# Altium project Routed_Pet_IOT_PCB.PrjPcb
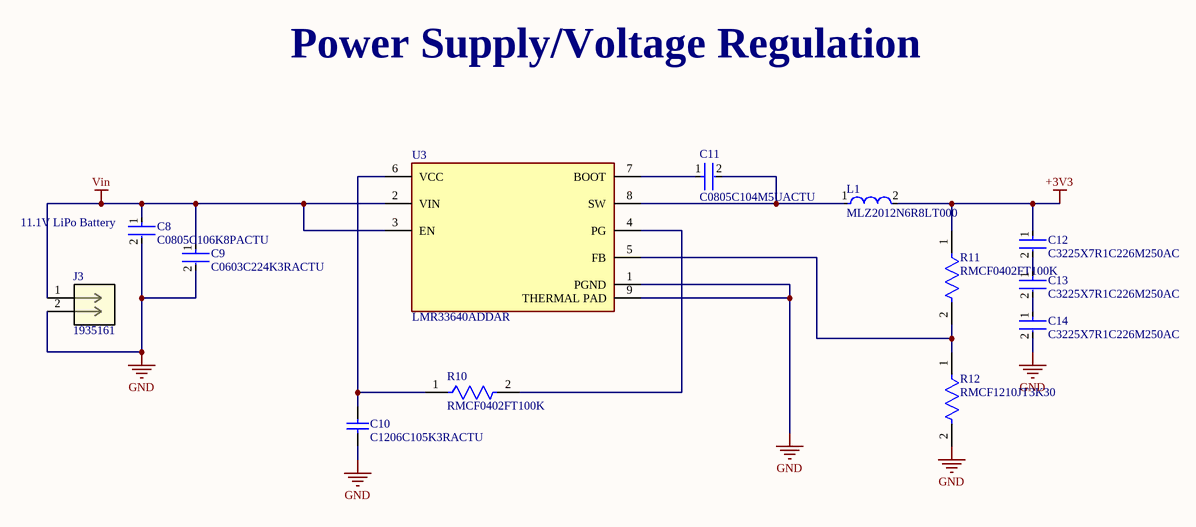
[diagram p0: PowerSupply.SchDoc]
3 sheets, 38 parts. Net scope: global (net labels, ports and power ports of the same name join across sheets).
Board file: PetTrackerPCB.PcbDoc
Sheets:
  PowerSupply.SchDoc
  Dataflow.SchDoc
  EC25.SchDoc

## Sheet PowerSupply.SchDoc
size A; SheetNumber: 1; SheetTotal: 3

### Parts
C8  C0805C106K8PACTU  [FP-C0805C-DG-MFG]
C9  C0603C224K3RACTU  [FP-C0603C-CF-MFG]
C10  C1206C105K3RACTU  [CAPC3216X180X50ML20T25]
C11  C0805C104M5UACTU  [FP-C0805C104M5UACTU-MFG]
C12  C3225X7R1C226M250AC  [FP-C3225-250-0_4-IPC_B]
C13  C3225X7R1C226M250AC  [FP-C3225-250-0_4-IPC_B]
C14  C3225X7R1C226M250AC  [FP-C3225-250-0_4-IPC_B]
J3  1935161  [CONN_1935161_PXC]
L1  MLZ2012N6R8LT000  [FP-MLZ2012-0_85-IPC_A]
R10  RMCF0402FT100K  [FP-RMCF0402-IPC_C]
R11  RMCF0402FT100K  [FP-RMCF0402-IPC_C]
R12  RMCF1210JT3K30  [FP-RMCF1210-IPC_A]
U3  LMR33640ADDAR  [FP-DDA0008J-IPC_A]

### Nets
+3V3: C12.1 L1.2 R11.1
GND: C8.2 C9.2 C10.1 C14.2 J3.2 R12.2 U3.1(PGND) U3.9(THERMAL_PAD)
Vin: C8.1 C9.1 J3.1 U3.2(VIN) U3.3(EN)
NetC10_2: C10.2 R10.1 U3.6(VCC)
NetC11_1: C11.1 U3.7(BOOT)
NetC11_2: C11.2 L1.1 U3.8(SW)
NetC12_2: C12.2 C13.1
NetC13_2: C13.2 C14.1
NetR10_2: R10.2 U3.4(PG)
NetR11_2: R11.2 R12.1 U3.5(FB)

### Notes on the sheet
- Power Supply/Voltage Regulation
- (near C8) 11.1V LiPo Battery

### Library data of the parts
C8 = CMP-2007-03243-2: CAP CER 10UF 10V X5R 0805; Manufacturer: Kemet; 3DS Part Number: 220-00001; Tolerance: 10%; Temperature Coefficient: 15%; Material: Ceramic
C9 = CMP-2006-03146-2: CAP CER 0.22UF 25V 10% X7R 0603; Manufacturer: KEMET; Temperature Coefficient: 30ppm/°C; Value: 0.22 μF; Material: Ceramic; Description: C0603 0.22 μF X7R 30ppm/°C 10.00% 25 V; Tolerance: 0.1; Automotive Grade: Grade 1
C10 = CMP-2000-04991-1: Chip Capacitor, 1 uF, +/- 10%, 25 V, -55 to 125 degC, 1206 (3216 Metric), RoHS, Tape and Reel; Manufacturer: Kemet; Temperature Coefficient / Code: +/-15%; Capacitance: 1uF; Dielectric: X7R; Voltage Rating DC: 25V; Capacitance - nF: 1000nF; Class: Class1; Case Length: 3.2mm; Type: SMDMLCCX7R6.3-250VDCCommericalGrade; Case Width: 1.6mm
C11 = CMP-2007-03742-2: CAP CER 0.1UF 50V Z5U 0805; Dielectric Material: Ceramic; Tolerance: 20%; Dissipation Factor: 4%; Capacitance: 100nF
C12-C14 = CMP-2000-06052-2: Multilayer Ceramic Capacitors 22uF ±20% 16V X7R SMD 1210
J3 = 1935161: Ceramic Capacitor, Multilayer, Ceramic, 16V, 10% +Tol, 10% -Tol, X5R, 15% TC, 10uF, Surface Mount, 0805; Mfr_Name: Phoenix Contact; Manufacturer: Samsung; Manufacturer Part Number: CL21A106KOQNNNE; Multilayer: Yes
L1 = CMP-08253-000092-1: Shielded Multilayer Inductor 6.8uH ±20% 550mA 325mΩ SMD 0805; Test Frequency: 2MHz; Self Resonant Frequency: 60MHz; Saturation Current: 110mA; Core Material: Ferrite; DC Resistance (DCR): 250mR
R10 R11 = CMP-2000-06984-2: 100kΩ ±1% 0.063W 0402 Thick Film Chip Resistor AEC-Q200 compliant; Max Power Dissipation: 63mW; Resistance: 100kR; Temperature Coefficient: 100ppm/°C; Power Rating: 62.5mW
R12 = CMP-26527-001928-1: 3.3kΩ ±5% 0.5W 1210 Thick Film Chip Resistor AEC-Q200 compliant; Temperature Coefficient: 200ppm/°C; Resistance: 3.3kR; Max Power Dissipation: 333mW
U3 = CMP-04918-000399-1: 36V 4A 400KHZ REGULATOR

## Sheet Dataflow.SchDoc
size A3; SheetNumber: 2; SheetTotal: 3
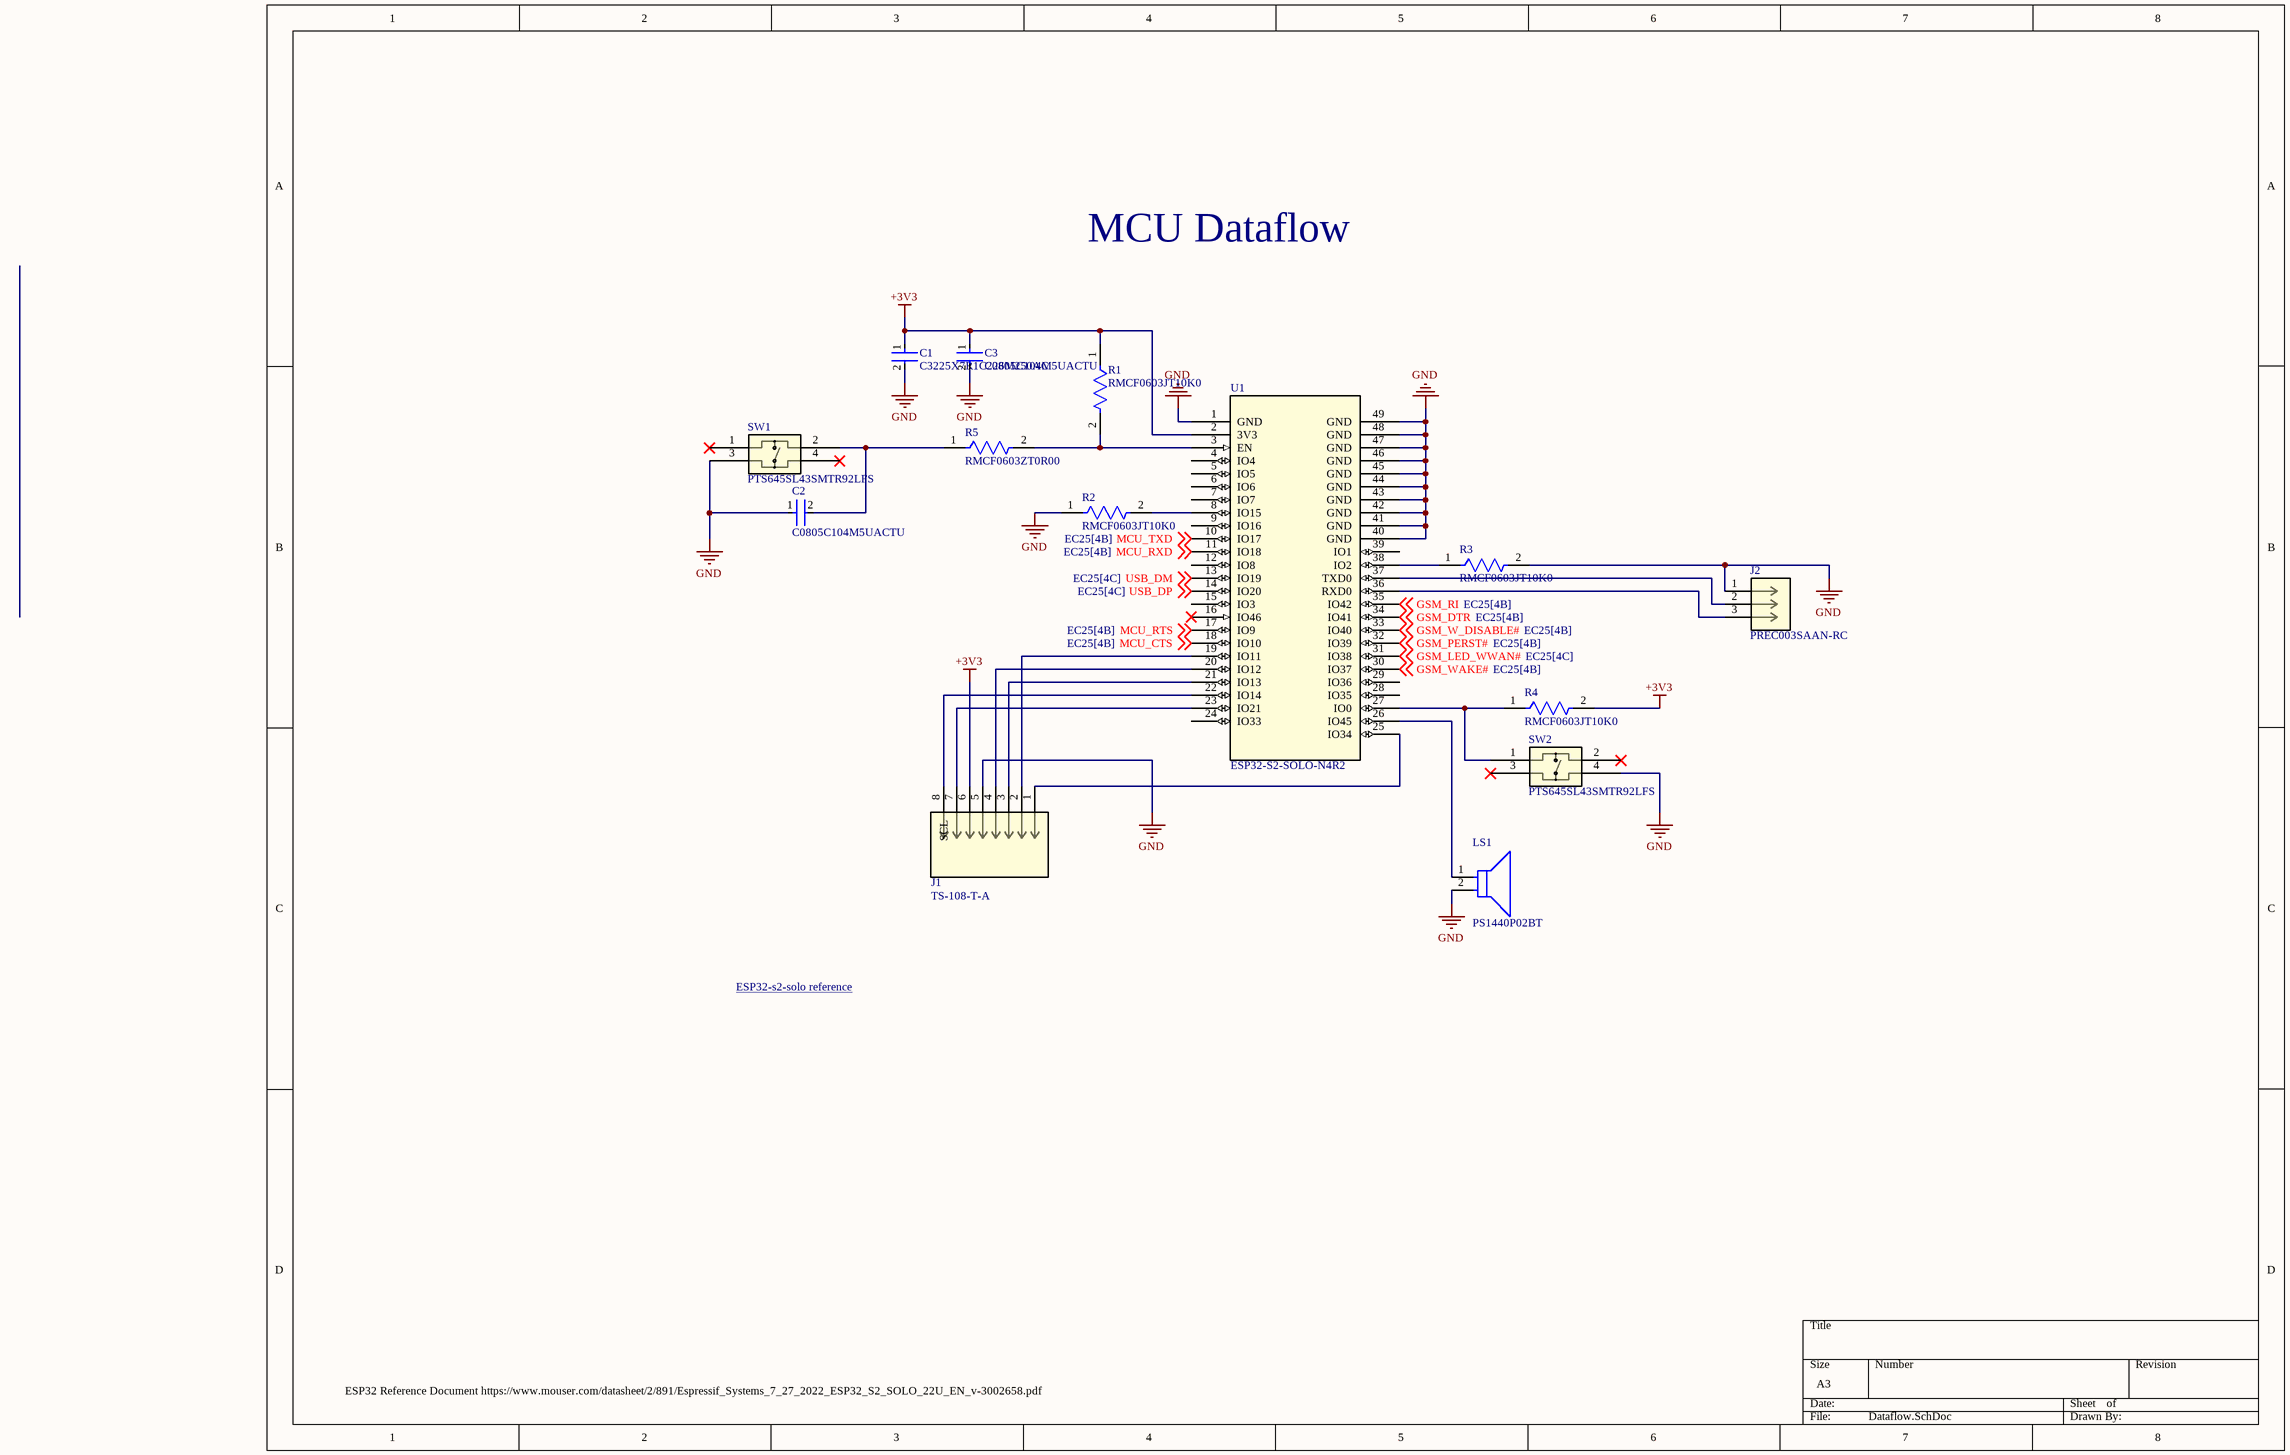
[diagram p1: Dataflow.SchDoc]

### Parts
C1  C3225X7R1C226M250AC  [FP-C3225-250-0_4-IPC_B]
C2  C0805C104M5UACTU  [FP-C0805C104M5UACTU-MFG]
C3  C0805C104M5UACTU  [FP-C0805C104M5UACTU-MFG]
J1  TS-108-T-A  [CON8_1X8_TU_HTS_SAI]
J2  PREC003SAAN-RC  [CONN_PREC003SAAN-RC_SUL]
LS1  PS1440P02BT  [FP-PS1440P02BT-MFG]
R1  RMCF0603JT10K0  [FP-RMCF0603-IPC_C]
R2  RMCF0603JT10K0  [FP-RMCF0603-IPC_C]
R3  RMCF0603JT10K0  [FP-RMCF0603-IPC_C]
R4  RMCF0603JT10K0  [FP-RMCF0603-IPC_C]
R5  RMCF0603ZT0R00  [FP-RMCF0603-MFG]
SW1  PTS645SL43SMTR92LFS  [PTS645SL43SMTR92LFS_CNK]
SW2  PTS645SL43SMTR92LFS  [PTS645SL43SMTR92LFS_CNK]
U1  ESP32-S2-SOLO-N4R2  [MOD41_ESP32-S2-SOLO_EXP]

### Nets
+3V3: C1.1 C3.1 J1.6(+3V3) R1.1 R4.2 U1.2(3V3)
GND: C1.2 C2.1 C3.2 J1.5(GND) J2.1 LS1.2 R2.1 R3.2 SW1.3 SW2.4 U1.1(GND) U1.40(GND) U1.41(GND) U1.42(GND) U1.43(GND) U1.44(GND) U1.45(GND) U1.46(GND) U1.47(GND) U1.48(GND) U1.49(GND)
GSM_DTR: U1.34(IO41) ; off-sheet GSM_DTR
GSM_LED_WWAN#: U1.31(IO38) ; off-sheet GSM_LED_WWAN#
GSM_PERST#: U1.32(IO39) ; off-sheet GSM_PERST#
GSM_RI: U1.35(IO42) ; off-sheet GSM_RI
GSM_W_DISABLE#: U1.33(IO40) ; off-sheet GSM_W_DISABLE#
GSM_WAKE#: U1.30(IO37) ; off-sheet GSM_WAKE#
MCU_CTS: U1.18(IO10) ; off-sheet MCU_CTS
MCU_RTS: U1.17(IO9) ; off-sheet MCU_RTS
MCU_RXD: U1.11(IO18) ; off-sheet MCU_RXD
MCU_TXD: U1.10(IO17) ; off-sheet MCU_TXD
USB_DM: U1.13(IO19) ; off-sheet USB_DM
USB_DP: U1.14(IO20) ; off-sheet USB_DP
NetC2_2: C2.2 R5.1 SW1.2
NetJ1_1: J1.1(CS) U1.25(IO34)
NetJ1_2: J1.2(MOSI) U1.19(IO11)
NetJ1_3: J1.3(MISO) U1.21(IO13)
NetJ1_4: J1.4(SCLK) U1.20(IO12)
NetJ1_7: J1.7(SDA) U1.23(IO21)
NetJ1_8: J1.8(SCL) U1.22(IO14)
NetJ2_2: J2.2 U1.37(TXD0)
NetJ2_3: J2.3 U1.36(RXD0)
NetLS1_1: LS1.1 U1.26(IO45)
NetR1_2: R1.2 R5.2 U1.3(EN)
NetR2_2: R2.2 U1.8(IO15)
NetR3_1: R3.1 U1.38(IO2)
NetR4_1: R4.1 SW2.1 U1.27(IO0)

Not connected (* = marked no-connect by the designer): SW1 1* 4*; SW2 2* 3*; U1 4(IO4) 5(IO5) 6(IO6) 7(IO7) 9(IO16) 12(IO8) 15(IO3) 16(IO46)* 24(IO33) 28(IO35) 29(IO36) 39(IO1)

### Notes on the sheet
- MCU Dataflow
- ESP32-s2-solo reference <https://www.espressif.com/sites/default/files/documentation/esp32-s2-solo-2_esp32-s2-solo-2u_datasheet_en.pdf>
- ESP32 Reference Document https://www.mouser.com/datasheet/2/891/Espressif_Systems_7_27_2022_ESP32_S2_SOLO_22U_EN_v-3002658.pdf

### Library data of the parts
C1 = CMP-2000-06052-2: as C12 on sheet PowerSupply
C2 C3 = CMP-2007-03742-2: as C11 on sheet PowerSupply
J1 = TS-108-T-A: No Description Available; Mfr_Name: Samtec Inc
J2 = PREC003SAAN-RC: No Description Available; Mfr_Name: Sullins
LS1 = CMP-08413-000003-1: AUDIO PIEZO TRANSDUCER 30V TH; Self Resonant Frequency: 4kHz; Washable: No; Voltage Rating (DC): 3V; Number of Terminals/Pins: 2
R1-R4 = CMP-26527-002098-1: 10kΩ ±5% 0.1W 0603 Thick Film Chip Resistor AEC-Q200 compliant; Power Rating: 100mW; Temperature Coefficient: 100ppm/°C; Resistance: 10kR
R5 = CMP-26527-000011-1: RES 0 OHM JUMPER 1/10W 0603; Manufacturer: Stackpole; Power Rating: 0.1W; Voltage Rating: 75V; Resistance: 0mΩ; Automotive Grade: Grade 0; Value: 0mΩ
SW1 SW2 = PTS645SL43SMTR92LFS: No Description Available; Mfr_Name: C&K Components
U1 = ESP32-S2-SOLO-N4R2: No Description Available; Mfr_Name: Espressif Systems

## Sheet EC25.SchDoc
size A3; SheetNumber: 3; SheetTotal: 3
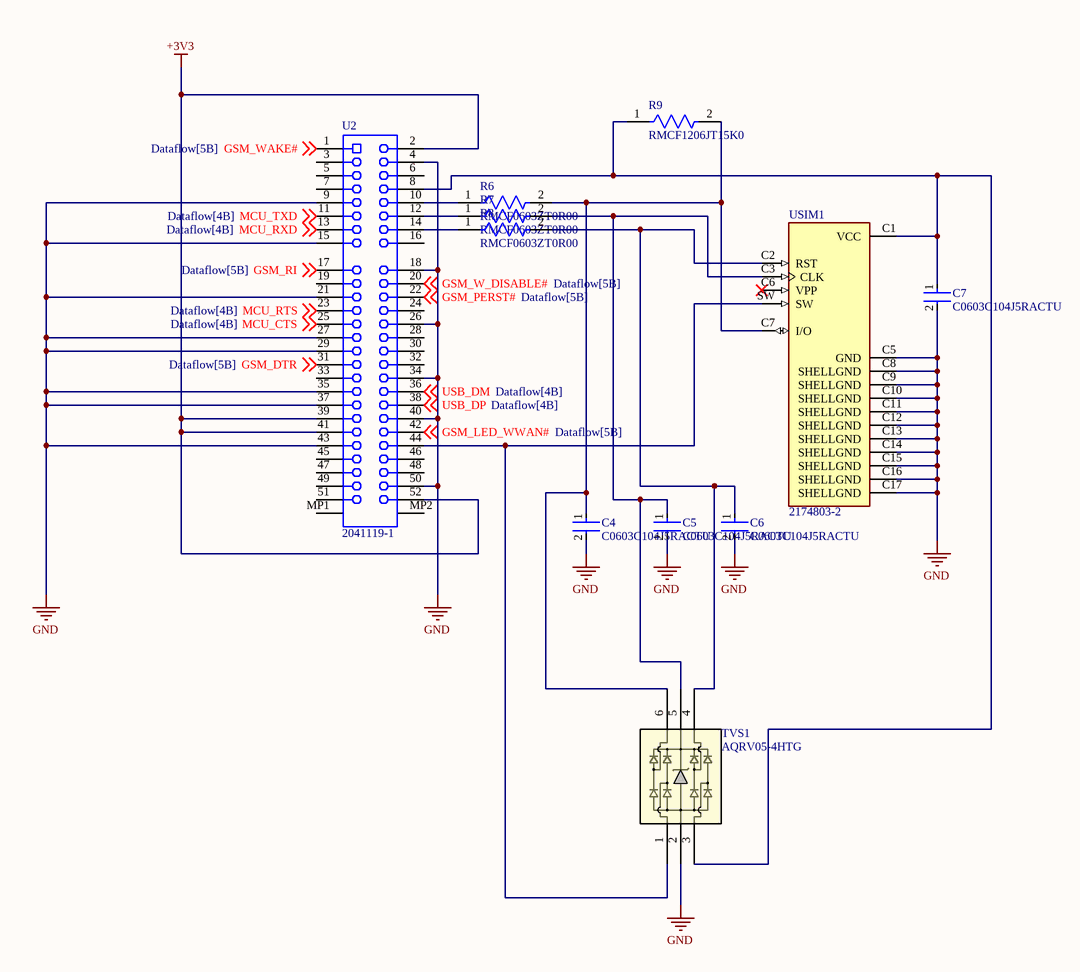
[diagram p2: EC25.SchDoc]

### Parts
C4  C0603C104J5RACTU  [FP-C0603C-CF-MFG]
C5  C0603C104J5RACTU  [FP-C0603C-CF-MFG]
C6  C0603C104J5RACTU  [FP-C0603C-CF-MFG]
C7  C0603C104J5RACTU  [FP-C0603C-CF-MFG]
R6  RMCF0603ZT0R00  [FP-RMCF0603-MFG]
R7  RMCF0603ZT0R00  [FP-RMCF0603-MFG]
R8  RMCF0603ZT0R00  [FP-RMCF0603-MFG]
R9  RMCF1206JT15K0  [FP-RMCF1206-IPC_A]
TVS1  AQRV05-4HTG  [SOT23-6_LTF]
U2  2041119-1  [TECO-2041119-1_3_V]
USIM1  2174803-2  [CONN_2174803-2]

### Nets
+3V3: U2.2 U2.39 U2.41 U2.52
GND: C4.2 C5.2 C6.2 C7.2 TVS1.2 U2.4 U2.9 U2.15 U2.18 U2.21 U2.26 U2.27 U2.29 U2.34 U2.35 U2.37 U2.40 U2.43 U2.50 USIM1.C5(GND) USIM1.C8(SHELLGND) USIM1.C9(SHELLGND) USIM1.C10(SHELLGND) USIM1.C11(SHELLGND) USIM1.C12(SHELLGND) USIM1.C13(SHELLGND) USIM1.C14(SHELLGND) USIM1.C15(SHELLGND) USIM1.C16(SHELLGND) USIM1.C17(SHELLGND)
GSM_DTR: U2.31 ; off-sheet GSM_DTR
GSM_LED_WWAN#: U2.42 ; off-sheet GSM_LED_WWAN#
GSM_PERST#: U2.22 ; off-sheet GSM_PERST#
GSM_RI: U2.17 ; off-sheet GSM_RI
GSM_W_DISABLE#: U2.20 ; off-sheet GSM_W_DISABLE#
GSM_WAKE#: U2.1 ; off-sheet GSM_WAKE#
MCU_CTS: U2.25 ; off-sheet MCU_CTS
MCU_RTS: U2.23 ; off-sheet MCU_RTS
MCU_RXD: U2.13 ; off-sheet MCU_RXD
MCU_TXD: U2.11 ; off-sheet MCU_TXD
USB_DM: U2.36 ; off-sheet USB_DM
USB_DP: U2.38 ; off-sheet USB_DP
NetC4_1: C4.1 R6.2 R9.2 TVS1.6 USIM1.C7(I/O)
NetC5_1: C5.1 R7.2 TVS1.5 USIM1.C3(CLK)
NetC6_1: C6.1 R8.2 TVS1.4 USIM1.C2(RST)
NetC7_1: C7.1 R9.1 TVS1.3 U2.8 USIM1.C1(VCC)
NetR6_1: R6.1 U2.10
NetR7_1: R7.1 U2.12
NetR8_1: R8.1 U2.14
NetTVS1_1: TVS1.1 U2.44 USIM1.SW

Not connected (* = marked no-connect by the designer): U2 3 5 6 7 16 19 24 28 30 32 33 45 46 47 48 49 51 MP1 MP2; USIM1 C6(VPP)*

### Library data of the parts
C4-C7 = CMP-2006-03056-2: CAP CER 0.1UF 50V 5% X7R 0603; Manufacturer: KEMET; Automotive Grade: Grade 1; Tolerance: 0.05; Capacitance: 0.10 μF; Value: 0.10 μF; Material: Ceramic; Temperature Coefficient: 30ppm/°C; Description: C0603 0.10 μF X7R 30ppm/°C 5.00% 50 V
R6-R8 = CMP-26527-000011-1: RES 0 OHM JUMPER 1/10W 0603; Manufacturer: Stackpole; Description: 0 Ohms Jumper 0.1W, 1/10W Chip Resistor 0603 (1608 Metric) Automotive AEC-Q200 Thick Film; Power Rating: 0.1W; Voltage Rating: 75V; Resistance: 0mΩ; Automotive Grade: Grade 0; Value: 0mΩ
R9 = CMP-26527-001400-1: 15kΩ ±5% 0.25W 1206 Thick Film Chip Resistor AEC-Q200 compliant; Temperature Coefficient: 200ppm/°C; Resistance: 15kR; Power Rating: 250mW
TVS1 = AQRV05-4HTG: No Description Available; Mfr_Name: Littelfuse Inc
U2 = CMP-2011-00000-2: mSATA & PCI Express Mini Card Connector, Pitch 0.4 mm, 52 Position, Height 4 mm, RoHS, Tape and Reel; Manufacturer: TE Connectivity; Case\Package: SMD; Rows: 2; Contacts: 52
USIM1 = 2174803-2: CONNECTOR, SIM SOCKET, 6POS, 2.54MM; Connector Type:SIM Socket; Series:2174803;; Number_of_Positions: 6; Voltage_Rating: 10 VAC; Centerline_Pitch: 2.54 mm[.1 in]; MF: TE Connectivity

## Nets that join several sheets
+3V3: PowerSupply (C12.1 L1.2 R11.1), Dataflow (6 pins), EC25 (U2.2 U2.39 U2.41 U2.52)
GND: PowerSupply (8 pins), Dataflow (21 pins), EC25 (30 pins)
GSM_DTR: Dataflow (U1.34), EC25 (U2.31)
GSM_LED_WWAN#: Dataflow (U1.31), EC25 (U2.42)
GSM_PERST#: Dataflow (U1.32), EC25 (U2.22)
GSM_RI: Dataflow (U1.35), EC25 (U2.17)
GSM_W_DISABLE#: Dataflow (U1.33), EC25 (U2.20)
GSM_WAKE#: Dataflow (U1.30), EC25 (U2.1)
MCU_CTS: Dataflow (U1.18), EC25 (U2.25)
MCU_RTS: Dataflow (U1.17), EC25 (U2.23)
MCU_RXD: Dataflow (U1.11), EC25 (U2.13)
MCU_TXD: Dataflow (U1.10), EC25 (U2.11)
USB_DM: Dataflow (U1.13), EC25 (U2.36)
USB_DP: Dataflow (U1.14), EC25 (U2.38)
